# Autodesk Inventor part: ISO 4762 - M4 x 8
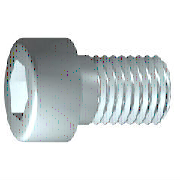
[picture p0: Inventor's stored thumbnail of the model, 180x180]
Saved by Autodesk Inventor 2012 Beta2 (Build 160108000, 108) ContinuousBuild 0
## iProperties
Created: 2010-11
Part Number: ISO 4762 - M4 x 8
Material: Stainless Steel, 440C
Description: Hexagon Socket Head Cap Screw
Document SubType Name: Modeling
Standard: ISO 4762
Designer: Beta-8540w
Standard Revision: Fourth edition 2004-03-01
Standards Organization: ISO
Language: en-US
Size Designation: M4 x 8
Categories: <MemberInstance><Categories><Category DisplayName="Fasteners" InternalName="e4da775c-781d-43d5-af7c-5136215cf5a6" Mnemonic="FSTN"><Category DisplayName="Bolts"
Density: 7.75 g/cm^3
IsCustomPart: 0
Author: Beta-8540w
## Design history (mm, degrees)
revolve "Body" stored, may be unused: angle "d10" = 90 deg
sketch "Sketch2"
  geometry: L1 (0, -4.9)-(0, 4.9) reference; L2 (-4.9, 0)-(4.9, 0) reference; L3 (1.732, 0)-(0.866, -1.5); L4 (0.866, -1.5)-(-0.866, -1.5); L5 (-0.866, -1.5)-(-1.732, 0); L6 (-1.732, 0)-(-0.866, 1.5); L7 (-0.866, 1.5)-(0.866, 1.5); L8 (0.866, 1.5)-(1.732, 0); 2 further points
  constraints: 12 end point, 1 coincident, 1 horizontal alignment, 1 point on line, 12 other
extrude "Slot" join sketch "Sketch2" stored distance "d11" = 10; taper "d12" = 0 deg
workplane "Work Plane1"
fillet "Fillet2" dims "d30" = 0.1 (= R)
body "Solid1"
fillet "Fillet1" dims "d17" = 0.4 (= RR)
feature "Thread" dims "d13" = 6.25 (= GEL), "d14" = 0
chamfer "Chamfer1" distance "d15" = 0.42941 (= -0.5 x SPD + 0.5 x GD); stored, may be unused: second distance "d16" = 0.42941 (= GUL), angle "d27" = 45 deg
sketch "Sketch1"
  geometry: L1 (-1, 0)-(8, 0); L2 (8, 0)-(8, 2); L3 (8, 2)-(1.75, 2); L4 (1.75, 2)-(1.32, 2); L5 (1.32, 2)-(0, 2); L6 (0, 2)-(0, 3.5); L7 (0, 3.5)-(-4, 3.5); L8 (-4, 3.5)-(-4, 1.732); L9 (-4, 1.732)-(-2, 1.732); L10 (-2, 1.732)-(-1, 0); L11 (-6.4, 0)-(10.4, 0) reference; L12 (0, -0.7)-(0, 4.2) reference; L13 (1.75, 2)-(0, 2)
  constraints: 22 end point, 6 parallel, 2 collinear, 2 perpendicular, 1 horizontal, 1 point on line
  dimensions: "d1" = 6.25 distance from line of L3.end L2 (= GEL); "d2" = 0.42952 distance of L4.end L3.end (computed from GAL); "d3" = 4 distance between parallel lines of L8 L6 (= KOH); "d4" = 2 distance of L8.end L9.end (= INTI); "d5" = 60 deg angle of L10 L1; "d6" = 4 diameter of L3 L1 (= GD); "d7" = 4 diameter of L5 L1 (= BDM); "d8" = 3.4641 diameter of L9 L1 (= 1.1547 x SW); "d9" = 7 diameter of L7 L1 (= KOD); "d26" = 8 distance between parallel lines of L12 L2 (= NLG)
other parameters: "GD" = 4 [user parameter; used in 2 equation terms], "NLG" = 8 [user parameter; used in 1 equation term], "GEL" = 6.25 [user parameter; used in 2 equation terms], "KOD" = 7 [user parameter; used in 1 equation term], "KOH" = 4 [user parameter; used in 1 equation term], "INTI" = 2 [user parameter; used in 1 equation term], "GAL" = 0.42941 (= 0.61345 x PTC) [user parameter; used in 1 equation term], "GUL" = 0.42941 (= 0.61345 x PTC) [user parameter; used in 1 equation term], "BDM" = 4 (= NND) [user parameter; used in 1 equation term], "SW" = 3 [user parameter; used in 2 equation terms], "RR" = 0.4 [user parameter; used in 1 equation term], "SPD" = 3.14117 (= NND - 1.2269 x PTC) [user parameter; used in 1 equation term], "d19" = 0, "d28" = 0, "d29" = 0, "R" = 0.1 [user parameter; used in 1 equation term], "TOA" = 30 deg [user parameter], "GD1" = 3.14117 (= THREADDIA - 1.2269 x PTC) [user parameter], "THREADDIA" = 4 [user parameter; used in 1 equation term], "FAWI" = 45 deg [user parameter], "TPU" = 14.28571 (computed from PTC) [user parameter], "PTC" = 0.7 [user parameter; used in 5 equation terms], "NND" = 4 [user parameter; used in 2 equation terms], "E0" = 3.465 (= 1.155 x SW) [user parameter]
